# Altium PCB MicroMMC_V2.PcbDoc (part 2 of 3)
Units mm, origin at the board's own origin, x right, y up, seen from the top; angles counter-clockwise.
Board outline 100.01 x 100 mm, 4 copper layers (TOP01, GND02, POWER03, BOTTOM04); 302 components, 195 nets, 1017 pads, 817 vias.
Unrouted connection lines stored in the file: 7.
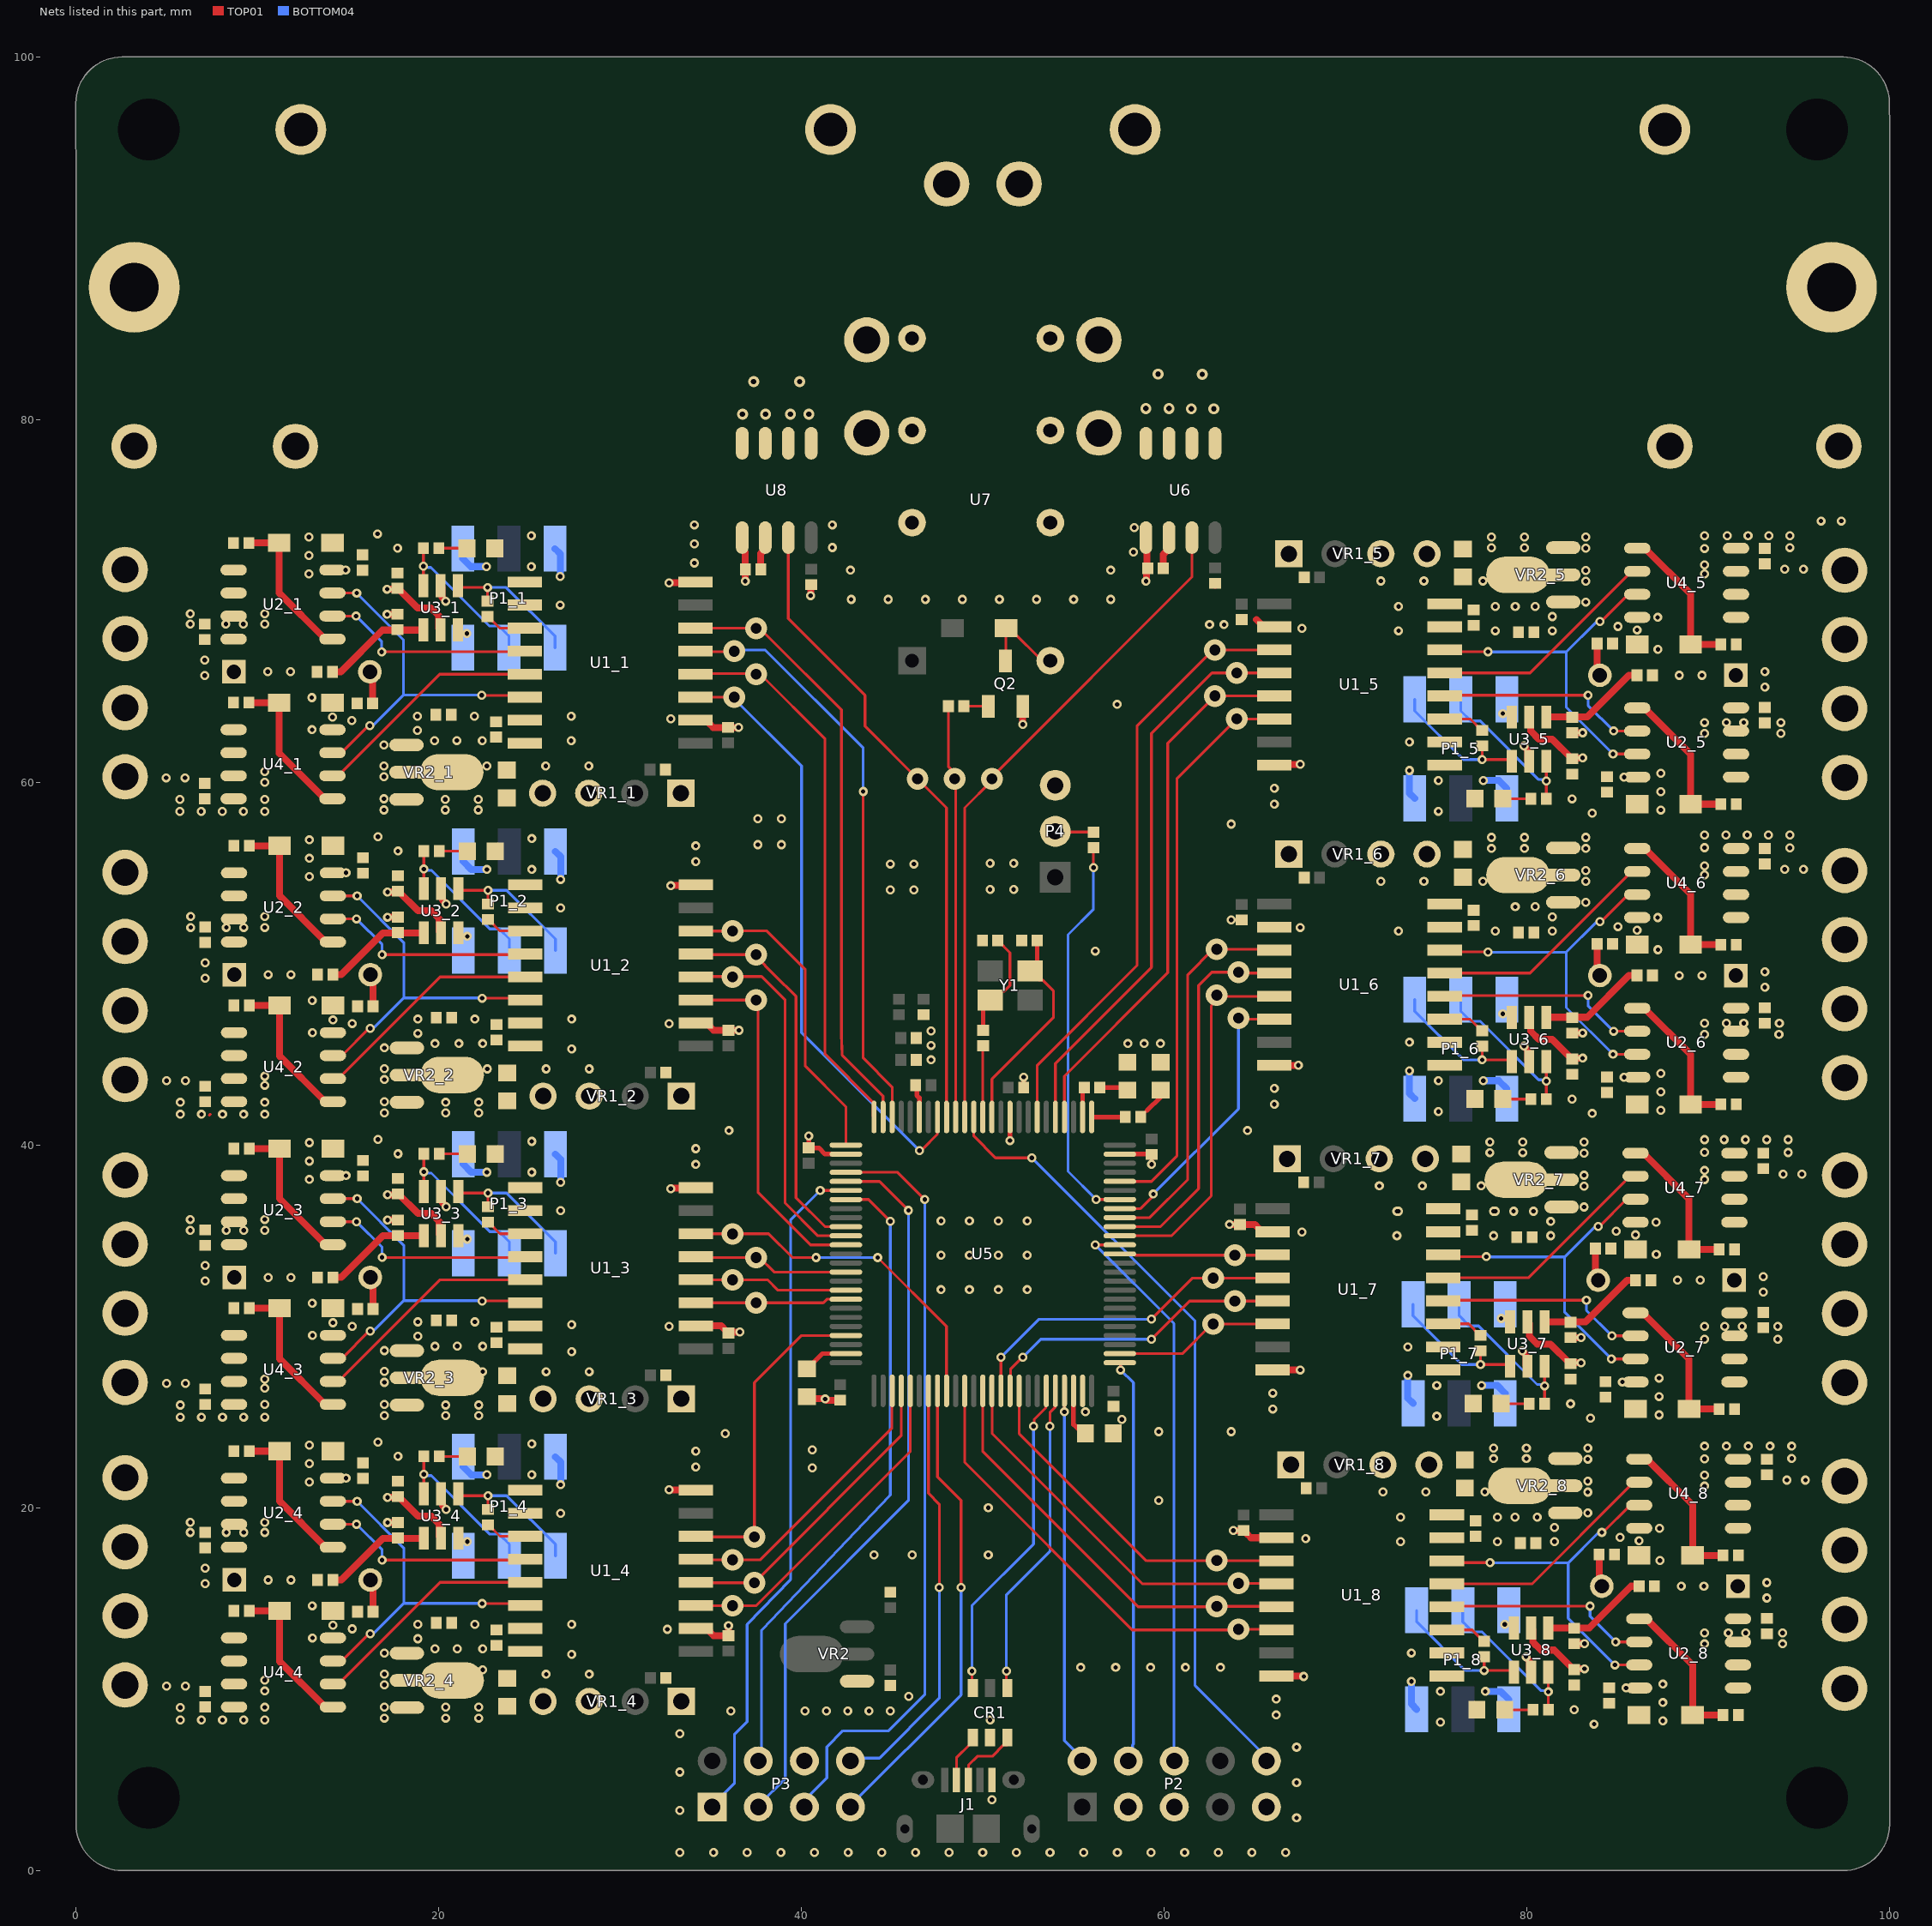
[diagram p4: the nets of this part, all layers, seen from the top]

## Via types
v1: diameter 0.5, hole 0.25, TOP01 to BOTTOM04, tented both sides, 760 vias
v2: diameter 1.2, hole 0.6, TOP01 to BOTTOM04, 35 vias
v3: diameter 0.6, hole 0.3, TOP01 to BOTTOM04, tented both sides, 12 vias
v4: diameter 0.5, hole 0.25, TOP01 to BOTTOM04, 10 vias

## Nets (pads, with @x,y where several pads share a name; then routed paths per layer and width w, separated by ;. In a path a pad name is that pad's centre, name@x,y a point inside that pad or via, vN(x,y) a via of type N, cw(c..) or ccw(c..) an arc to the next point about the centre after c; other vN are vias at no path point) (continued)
+5V_SM: C2_1.2 C2_2.2 C2_3.2 C2_4.2 C2_5.2 C2_6.2 C2_7.2 C2_8.2 C9_1.2 C9_2.2 C9_3.2 C9_4.2 C9_5.2 C9_6.2 C9_7.2 C9_8.2 C10_1.2 C10_2.2 C10_3.2 C10_4.2 C10_5.2 C10_6.2 C10_7.2 C10_8.2 P1_1.2 P1_2.2 P1_3.2 P1_4.2 P1_5.2 P1_6.2 P1_7.2 P1_8.2 U1_1.10 U1_1.16 U1_2.10 U1_2.16 U1_3.10 U1_3.16 U1_4.10 U1_4.16 U1_5.10 U1_5.16 U1_6.10 U1_6.16 U1_7.10 U1_7.16 U1_8.10 U1_8.16 U3_1.5 U3_2.5 U3_3.5 U3_4.5 U3_5.5 U3_6.5 U3_7.5 U3_8.5 VR2_1.1 VR2_2.1 VR2_3.1 VR2_4.1 VR2_5.1 VR2_6.1 VR2_7.1 VR2_8.1 | length 53
  TOP01 w0.152: C10_1.2@17.702,70.654 C10_1.2@17.75,70.702 ; C10_4.2@17.726,20.574 C10_4.2@17.774,20.622 ; C10_3.2@17.726,37.259 C10_3.2@17.774,37.306 ; C10_2.2@17.726,53.954 C10_2.2@17.774,54.002 ; U3_1.5@20.003,68.501 U3_1.5@20.1,68.405 ; U3_4.5@20.027,18.421 U3_4.5@20.123,18.325 ; U3_3.5@20.027,35.106 U3_3.5@20.123,35.01 ; U3_2.5@20.027,51.801 U3_2.5@20.123,51.705 ; U3_7.5@80.032,30.246 U3_7.5@80.129,30.149 ; U3_6.5@80.123,47.046 U3_6.5@80.22,46.949 ; U3_5.5@80.123,63.602 U3_5.5@80.22,63.505 ; U3_8.5@80.233,13.372 U3_8.5@80.33,13.276 ; C10_7.2@82.382,27.949 C10_7.2@82.429,27.997 ; C10_6.2@82.473,44.749 C10_6.2@82.52,44.797 ; C10_5.2@82.473,61.305 C10_5.2@82.52,61.353 ; C10_8.2@82.583,11.075 C10_8.2@82.631,11.123
  TOP01 w0.381: v1(17.15,70.654) C10_1.2@17.702,70.654 ; v1(17.174,20.574) C10_4.2@17.726,20.574 ; v1(17.174,37.259) C10_3.2@17.726,37.259 ; v1(17.174,53.954) C10_2.2@17.726,53.954 ; C10_1.2@17.75,70.702 18.828,69.624 19.558,69.624 20.003,69.179 U3_1.5@20.003,68.501 ; C10_4.2@17.774,20.622 18.851,19.544 19.582,19.544 20.027,19.099 U3_4.5@20.027,18.421 ; C10_3.2@17.774,37.306 18.851,36.229 19.582,36.229 20.027,35.784 U3_3.5@20.027,35.106 ; C10_2.2@17.774,54.002 18.851,52.924 19.582,52.924 20.027,52.479 U3_2.5@20.027,51.801 ; U1_1.16@24.1,62.16 U1_1.16@24.75,62.16 ; U1_4.16@24.123,12.08 U1_4.16@24.773,12.08 ; U1_3.16@24.123,28.765 U1_3.16@24.773,28.765 ; U1_2.16@24.123,45.46 U1_2.16@24.773,45.46 ; U1_7.16@75.382,36.491 U1_7.16@76.032,36.491 ; U1_6.16@75.473,53.291 U1_6.16@76.123,53.291 ; U1_5.16@75.473,69.847 U1_5.16@76.123,69.847 ; U1_8.16@75.583,19.617 U1_8.16@76.233,19.617 ; U3_7.5@80.129,30.149 80.129,29.472 80.573,29.027 81.304,29.027 C10_7.2@82.382,27.949 ; U3_6.5@80.22,46.949 80.22,46.272 80.664,45.827 81.395,45.827 C10_6.2@82.473,44.749 ; U3_5.5@80.22,63.505 80.22,62.828 80.664,62.383 81.395,62.383 C10_5.2@82.473,61.305 ; U3_8.5@80.33,13.276 80.33,12.598 80.775,12.153 81.506,12.153 C10_8.2@82.583,11.075 ; C10_7.2@82.429,27.997 v1(82.982,27.997) ; C10_6.2@82.52,44.797 v1(83.073,44.797) ; C10_5.2@82.52,61.353 v1(83.073,61.353) ; C10_8.2@82.631,11.123 v1(83.183,11.123)
  BOTTOM04 w0.381: P1_1.2@26.407,72.89 26.7,72.598 v1(26.7,71.35) ; P1_4.2@26.431,22.81 26.724,22.518 v1(26.724,21.27) ; P1_3.2@26.431,39.495 26.724,39.202 v1(26.724,37.955) ; P1_2.2@26.431,56.19 26.724,55.898 v1(26.724,54.65) ; v1(73.432,27.301) 73.432,26.053 P1_7.2@73.725,25.76 ; v1(73.523,44.101) 73.523,42.853 P1_6.2@73.815,42.561 ; v1(73.523,60.657) 73.523,59.409 P1_5.2@73.815,59.117 ; v1(73.633,10.427) 73.633,9.179 P1_8.2@73.926,8.887
  other v1: 17.001,11.982 73.633,11.997 19.789,12.22 21.016,12.229 22.424,12.22 18.84,12.782 18.84,13.567 81.517,18.13 81.517,18.915 78.371,19.477 79.341,19.477 80.568,19.477 26.724,19.7 83.356,19.715 17.001,28.667 73.432,28.871 19.789,28.905 21.016,28.914 22.424,28.905 18.84,29.467 18.84,30.252 81.316,35.004 81.316,35.789 78.17,36.351 78.26,36.351 79.268,36.351 80.366,36.351 26.724,36.385 83.155,36.589 17.001,45.362 19.789,45.6 21.106,45.6 22.424,45.6 73.523,45.671 18.84,46.162 18.84,46.947 81.407,51.804 81.407,52.589 26.724,53.08 79.359,53.142 80.457,53.151 83.246,53.389 16.977,62.062 73.523,62.227 19.765,62.3 20.992,62.309 22.4,62.3 18.816,62.862 18.816,63.647 81.407,68.36 81.407,69.145 78.26,69.698 79.359,69.698 80.457,69.698 26.7,69.78 83.246,69.945
+12_SM: C3_1.2 C3_2.2 C3_3.2 C3_4.2 C3_5.2 C3_6.2 C3_7.2 C3_8.2 C4_1.2 C4_2.2 C4_3.2 C4_4.2 C4_5.2 C4_6.2 C4_7.2 C4_8.2 C6_1.2 C6_2.2 C6_3.2 C6_4.2 C6_5.2 C6_6.2 C6_7.2 C6_8.2 D1_1.1 D1_2.1 D1_3.1 D1_4.1 D1_5.1 D1_6.1 D1_7.1 D1_8.1 D2_1.1 D2_2.1 D2_3.1 D2_4.1 D2_5.1 D2_6.1 D2_7.1 D2_8.1 U2_1.4 U2_2.4 U2_3.4 U2_4.4 U2_5.4 U2_6.4 U2_7.4 U2_8.4 U4_1.4 U4_2.4 U4_3.4 U4_4.4 U4_5.4 U4_6.4 U4_7.4 U4_8.4 VR1_1.4 VR1_2.4 VR1_3.4 VR1_4.4 VR1_5.4 VR1_6.4 VR1_7.4 VR1_8.4 VR2_1.3 VR2_2.3 VR2_3.3 VR2_4.3 VR2_5.3 VR2_6.3 VR2_7.3 VR2_8.3 | length 0.1
  TOP01 w0.381: D1_1.1@14.137,73.197 D1_1.1@14.145,73.205 ; D1_4.1@14.161,23.117 D1_4.1@14.169,23.125 ; D1_3.1@14.161,39.801 D1_3.1@14.169,39.81 ; D1_2.1@14.161,56.497 D1_2.1@14.169,56.505 ; D1_7.1@85.986,25.446 D1_7.1@85.995,25.454 ; D1_6.1@86.077,42.246 D1_6.1@86.086,42.254 ; D1_5.1@86.077,58.802 D1_5.1@86.086,58.81 ; D1_8.1@86.188,8.572 D1_8.1@86.196,8.58
  other v1: 87.495,8.247 17.001,8.402 20.382,8.402 22.197,8.402 17.001,9.015 20.382,9.015 22.197,9.015 87.495,9.262 85.471,10.065 87.495,10.277 13.036,12.825 15.224,13.325 14.169,13.52 13.019,14.597 87.338,17.1 86.188,18.177 85.133,18.372 87.321,18.872 12.861,21.42 14.886,21.632 12.861,22.435 83.356,22.682 78.16,22.715 79.975,22.715 78.16,23.294 79.975,23.294 83.356,23.294 12.861,23.45 17.001,25.087 20.382,25.087 22.197,25.087 87.294,25.121 20.382,25.667 22.197,25.667 17.001,25.7 87.294,26.136 85.27,26.939 87.294,27.151 13.036,29.51 15.224,30.01 14.169,30.205 13.019,31.282 87.136,33.974 85.986,35.051 84.932,35.246 87.12,35.746 12.861,38.105 14.886,38.317 12.861,39.12 83.155,39.556 77.959,39.589 79.774,39.589 12.861,40.135 77.959,40.168 79.774,40.168 83.155,40.168 17.001,41.782 20.382,41.782 22.197,41.782 87.385,41.921 20.382,42.362 22.197,42.362 17.001,42.395 87.385,42.936 85.361,43.739 87.385,43.951 13.036,46.205 15.224,46.705 14.169,46.9 13.019,47.977 87.227,50.774 86.077,51.851 85.023,52.046 87.211,52.546 12.861,54.8 14.886,55.012 12.861,55.815 78.05,56.356 79.864,56.356 83.246,56.356 12.861,56.83 78.05,56.968 79.864,56.968 83.246,56.968 16.977,58.482 20.358,58.482 22.173,58.482 87.385,58.477 20.358,59.062 22.173,59.062 16.977,59.095 87.385,59.492 85.361,60.295 87.385,60.507 13.012,62.905 15.2,63.405 14.145,63.6 12.995,64.677 87.227,67.33 86.077,68.407 85.023,68.602 87.211,69.102 12.838,71.5 14.862,71.712 12.838,72.515 83.246,72.912 78.05,72.945 79.864,72.945 12.838,73.53 78.05,73.524 79.864,73.524 83.246,73.524
ADC_I1: U5.15 U6.7 | length 37
  TOP01 w0.152: U5.15@49,41.55 49,58.6 v2@50.5,60.1 ; v2(50.5,60.2) 50.5,60.3 61.533,71.333 U6.7@61.533,73.5
ADC_I2: U5.17 U8.7 | length 35.6
  TOP01 w0.152: U8.7@39.27,73.5 39.27,69.03 43.5,64.8 43.5,63.1 v2(46.4,60.2) 48,58.6 U5.17@48,41.55
BOOT0: R5.1 U5.94 | length 21.7
  TOP01 w0.152: v1(56.1,55.3) R5.1@56.1,56.2 ; v1(56.25,37) U5.94@57.55,37
  BOTTOM04 w0.152: v1(56.1,55.3) 56.1,53 54.7,51.6 54.7,38.55 v1(56.25,37)
EN_1: U1_1.14 U2_1.3 U4_1.3 | length 20.1
  TOP01 w0.152: U4_1.3@14.137,61.635 14.632,61.635 16.131,63.134 v1(16.2,63.134) ; U2_1.3@14.137,70.442 v1(15.475,70.442) 15.508,70.442 v1@15.55,70.4 ; v1(22.365,64.8) 24.649,64.8 U1_1.14@24.75,64.7
  BOTTOM04 w0.152: v1(15.475,70.442) 18.05,67.867 18.05,64.814 ; v1(16.2,63.134) 16.267,63.201 16.437,63.201 18.05,64.814 ; v1(22.365,64.8) 22.351,64.814 18.05,64.814
EN_2: U1_2.14 U2_2.3 U4_2.3 | length 20.1
  TOP01 w0.152: U4_2.3@14.161,44.935 14.655,44.935 16.154,46.434 v1(16.224,46.434) ; U2_2.3@14.161,53.742 v1(15.499,53.742) 15.532,53.742 v1@15.574,53.7 ; v1(22.388,48.1) 24.673,48.1 U1_2.14@24.773,48
  BOTTOM04 w0.152: v1(15.499,53.742) 18.074,51.167 18.074,48.114 ; v1(16.224,46.434) 16.29,46.501 16.46,46.501 18.074,48.114 ; v1(22.388,48.1) 22.374,48.114 18.074,48.114
EN_3: U1_3.14 U2_3.3 U4_3.3 | length 20.1
  TOP01 w0.152: U4_3.3@14.161,28.24 14.655,28.24 16.154,29.739 v1(16.224,29.739) ; U2_3.3@14.161,37.047 v1(15.499,37.047) 15.532,37.047 v1@15.574,37.005 ; v1(22.388,31.405) 24.673,31.405 U1_3.14@24.773,31.305
  BOTTOM04 w0.152: v1(15.499,37.047) 18.074,34.472 18.074,31.419 ; v1(16.224,29.739) 16.29,29.805 16.46,29.805 18.074,31.419 ; v1(22.388,31.405) 22.374,31.419 18.074,31.419
EN_4: U1_4.14 U2_4.3 U4_4.3 | length 20.1
  TOP01 w0.152: U4_4.3@14.161,11.555 14.655,11.555 16.154,13.054 v1(16.224,13.054) ; U2_4.3@14.161,20.362 v1(15.499,20.362) 15.532,20.362 v1@15.574,20.32 ; v1(22.388,14.72) 24.673,14.72 U1_4.14@24.773,14.62
  BOTTOM04 w0.152: v1(15.499,20.362) 18.074,17.787 18.074,14.734 ; v1(16.224,13.054) 16.29,13.121 16.46,13.121 18.074,14.734 ; v1(22.388,14.72) 22.374,14.734 18.074,14.734
EN_5: U1_5.14 U2_5.3 U4_5.3 | length 20.1
  TOP01 w0.152: U1_5.14@75.473,67.307 75.573,67.207 v1(77.858,67.207) ; v1(84.023,68.873) 84.092,68.873 85.591,70.372 U4_5.3@86.086,70.372 ; v1@84.673,61.607 84.715,61.565 v1(84.748,61.565) U2_5.3@86.086,61.565
  BOTTOM04 w0.152: v1(77.858,67.207) 77.872,67.193 82.173,67.193 ; v1(84.023,68.873) 83.956,68.806 83.786,68.806 82.173,67.193 ; v1(84.748,61.565) 82.173,64.14 82.173,67.193
EN_6: U1_6.14 U2_6.3 U4_6.3 | length 20.1
  TOP01 w0.152: U1_6.14@75.473,50.751 75.573,50.651 v1(77.858,50.651) ; v1(84.023,52.317) 84.092,52.317 85.591,53.816 U4_6.3@86.086,53.816 ; v1@84.673,45.051 84.715,45.009 v1(84.748,45.009) U2_6.3@86.086,45.009
  BOTTOM04 w0.152: v1(77.858,50.651) 77.872,50.637 82.173,50.637 ; v1(84.023,52.317) 83.956,52.25 83.786,52.25 82.173,50.637 ; v1(84.748,45.009) 82.173,47.584 82.173,50.637
EN_7: U1_7.14 U2_7.3 U4_7.3 | length 20.1
  TOP01 w0.152: U1_7.14@75.382,33.951 75.482,33.851 v1(77.767,33.851) ; v1(83.932,35.517) 84.001,35.517 85.5,37.016 U4_7.3@85.995,37.016 ; v1@84.582,28.251 84.624,28.209 v1(84.657,28.209) U2_7.3@85.995,28.209
  BOTTOM04 w0.152: v1(77.767,33.851) 77.781,33.837 82.082,33.837 ; v1(83.932,35.517) 83.865,35.45 83.695,35.45 82.082,33.837 ; v1(84.657,28.209) 82.082,30.784 82.082,33.837
EN_8: U1_8.14 U2_8.3 U4_8.3 | length 20.1
  TOP01 w0.152: U1_8.14@75.583,17.077 75.684,16.977 v1(77.968,16.977) ; v1(84.133,18.643) 84.202,18.643 85.702,20.142 U4_8.3@86.196,20.142 ; v1@84.783,11.377 84.825,11.335 v1(84.858,11.335) U2_8.3@86.196,11.335
  BOTTOM04 w0.152: v1(77.968,16.977) 77.982,16.963 82.283,16.963 ; v1(84.133,18.643) 84.067,18.576 83.896,18.576 82.283,16.963 ; v1(84.858,11.335) 82.283,13.91 82.283,16.963
Filter_I1: C25.2 U6.6 | length 1.8
  TOP01 w0.381: C25.2@59.95,71.8 59.95,72.579 60.263,72.893 U6.6@60.263,73.5
Filter_I2: C27.2 U8.6 | length 1.9
  TOP01 w0.381: C27.2@37.753,71.75 37.753,72.616 38,72.864 U8.6@38,73.5
Fv_1: R1_1.1 U1_1.11 | length 2.3
  TOP01 w0.152: R1_1.1@22.69,69.143 22.715,69.143 23.348,68.51 U1_1.11@24.75,68.51
Fv_2: R1_2.1 U1_2.11 | length 2.3
  TOP01 w0.152: R1_2.1@22.713,52.443 22.738,52.443 23.371,51.81 U1_2.11@24.773,51.81
Fv_3: R1_3.1 U1_3.11 | length 2.3
  TOP01 w0.152: R1_3.1@22.713,35.748 22.738,35.748 23.371,35.115 U1_3.11@24.773,35.115
Fv_4: R1_4.1 U1_4.11 | length 2.3
  TOP01 w0.152: R1_4.1@22.713,19.063 22.738,19.063 23.371,18.43 U1_4.11@24.773,18.43
Fv_5: R1_5.1 U1_5.11 | length 2.3
  TOP01 w0.152: U1_5.11@75.473,63.497 76.875,63.497 77.508,62.864 R1_5.1@77.533,62.864
Fv_6: R1_6.1 U1_6.11 | length 2.3
  TOP01 w0.152: U1_6.11@75.473,46.941 76.875,46.941 77.508,46.308 R1_6.1@77.533,46.308
Fv_7: R1_7.1 U1_7.11 | length 2.3
  TOP01 w0.152: U1_7.11@75.382,30.141 76.784,30.141 77.417,29.508 R1_7.1@77.442,29.508
Fv_8: R1_8.1 U1_8.11 | length 2.3
  TOP01 w0.152: U1_8.11@75.583,13.267 76.985,13.267 77.618,12.634 R1_8.1@77.643,12.634
GND: C1_1.1 C1_2.1 C1_3.1 C1_4.1 C1_5.1 C1_6.1 C1_7.1 C1_8.1 C7_1.1 C7_2.1 C7_3.1 C7_4.1 C7_5.1 C7_6.1 C7_7.1 C7_8.1 C10.1 C11.1 C12.1 C13.1 C14.1 C15.1 C16.1 C17.1 C18.1 C19.2 C20.1 C21.1 C22.1 C23.1 C24.1 C25.1 C26.1 C27.1 C28.1 CR1.2 D4.K D5.K J1.5 P2.3 P2.5 P2.9 P3.6 P4.3 Q2.2 U1_1.2 U1_1.8 U1_2.2 U1_2.8 U1_3.2 U1_3.8 U1_4.2 U1_4.8 U1_5.2 U1_5.8 U1_6.2 U1_6.8 U1_7.2 U1_7.8 U1_8.2 U1_8.8 U5.10 U5.20 U5.27 U5.74 U5.99 U6.5 U8.5 VR1_1.1 VR1_2.1 VR1_3.1 VR1_4.1 VR1_5.1 VR1_6.1 VR1_7.1 VR1_8.1 VR2.1 | length 45.4
  TOP01 w0.152: v1@36.9,71.2 v1@36.903,71.203 ; v1(58.35,74.05) v1@58.388,74.012 ; U6.5@58.74,74.012 U6.5@58.993,73.759
  TOP01 w0.254: U1_1.8@34.125,71.075 U1_1.8@34.15,71.05 ; v1(40.4,40.5) 40.4,39.863 40.38,39.843 40.957,39.843 41.295,39.505 42.445,39.505 U5.27@42.45,39.5 ; C13.1@42.102,25.968 C13.1@42.134,25.936 ; C18.1@46.29,43.3 46.357,43.233 46.357,42.743 46.5,42.6 U5.20@46.5,41.55 ; v1(51.5,40.25) U5.10@51.5,41.55 ; C16.1@52.251,43.175 v1@52.251,43.5 ; U5.99@57.55,39.5 59.305,39.5 59.308,39.497 59.308,38.942 v1(59.305,38.939) ; U6.5@58.993,73.5 U6.5@58.993,73.759 ; v1@67.673,10.727 v1(67.7,10.7)
  TOP01 w0.381: v1(32.7,21) 32.715,20.985 34.158,20.985 U1_4.8@34.173,20.97 ; v1(32.7,71) 32.723,71.023 34.123,71.023 U1_1.8@34.15,71.05 ; v1(32.8,37.6) 32.823,37.623 34.141,37.623 U1_3.8@34.173,37.655 ; v1(32.8,54.3) 32.823,54.323 34.146,54.323 U1_2.8@34.173,54.35 ; U1_1.2@34.15,63.43 34.8,63.43 34.909,63.32 34.909,63.253 35.132,63.03 C7_1.1@35.95,63.03 v1(36.525,63.03) ; U1_4.2@34.173,13.35 34.823,13.35 34.933,13.24 34.933,13.173 35.156,12.95 C7_4.1@35.973,12.95 v1(35.973,13.5) ; U1_3.2@34.173,30.035 35.573,30.035 35.839,29.769 35.839,29.744 35.948,29.635 36.065,29.635 36.108,29.677 36.577,29.677 v1(36.6,29.7) ; U1_2.2@34.173,46.73 34.823,46.73 34.933,46.62 34.933,46.553 35.156,46.33 C7_2.1@35.973,46.33 v1(36.548,46.33) ; U8.5@36.73,73.5 36.791,73.439 36.791,72.803 36.903,72.691 36.903,71.885 v1@36.903,71.203 ; C23.1@40.3,26.13 40.407,26.023 41.277,26.023 v1(41.3,26) 41.332,26 41.396,25.936 C13.1@42.134,25.936 ; v1(40.5,70.3) 40.52,70.32 40.52,70.88 C28.1@40.54,70.9 ; v1(52.2,63.2) Q2.2@52.2,64.2 ; U6.5@58.993,73.5 59.047,73.447 59.047,71.853 C25.1@59.1,71.8 59.023,71.723 59.023,71.123 v1(59,71.1) ; C26.1@62.802,70.866 62.803,70.867 C26.1@62.803,70.975 ; v1(63.607,35.621) C7_7.1@64.182,35.621 64.999,35.621 65.223,35.398 65.223,35.33 65.332,35.221 U1_7.2@65.982,35.221 ; v1(63.808,18.747) C7_8.1@64.383,18.747 64.408,18.747 64.518,18.637 64.518,18.613 64.783,18.347 U1_8.2@66.183,18.347 ; 65.09,68.977 U1_5.2@65.314,68.754 ; U1_5.2@65.314,68.686 U1_5.2@65.423,68.577 ; U1_7.8@65.982,27.601 v1(67.5,27.6) ; U1_6.8@66.074,44.4 v1(67.4,44.4) ; U1_5.8@66.073,60.957 66.095,60.978 67.478,60.978 v1(67.5,61) ; U1_8.8@66.183,10.727 v1@67.673,10.727
  other v1: 33.295,1 35.151,1 37.006,1 38.862,1 40.717,1 42.573,1 44.429,1 46.284,1 48.14,1 49.995,1 51.851,1 53.706,1 55.562,1 57.417,1 59.273,1 61.128,1 62.984,1 64.84,1 66.695,1 67.3,2.9 33.295,3.314 50.5,3.9 67.3,4.85 33.295,5.427 67.3,6.8 33.295,7.54 50.4,8.3 66.183,8.577 36.1,8.8 40.2,8.8 41.375,8.8 42.55,8.8 43.725,8.8 44.9,8.8 66.183,9.45 45.92,9.603 55.4,11.2 57.325,11.2 59.25,11.2 61.175,11.2 63.1,11.2 32.6,13.3 44,17.4 46.1,17.4 50.3,17.4 67.8,18.3 50.3,20 59.7,20.4 40.6,22.2 34.173,22.247 34.173,23.12 40.6,23.2 35.8,24.1 59.7,24.2 63.7,24.2 57.665,24.877 55.66,25.291 65.982,25.451 65.982,26.324 32.7,30 47.697,32.03 49.259,32.03 50.859,32.03 52.45,32.03 47.697,33.923 49.259,33.923 50.859,33.923 52.45,33.923 67.6,35.2 47.697,35.823 49.259,35.823 50.859,35.823 52.45,35.823 34.173,38.932 34.173,39.805 36,40.8 64.6,40.8 66.073,42.251 66.073,43.124 52.251,43.75 47.14,44.7 47.14,45.5 58,45.6 58.9,45.6 59.8,45.6 47.14,46.3 32.7,46.7 56.2,50.7 67.5,52 63.698,52.421 44.9,55.5 34.173,55.627 34.173,56.5 63.7,57.7 37.6,58 66.073,58.807 66.073,59.68 32.8,63.5 57.4,64.3 67.6,68.5 62.5,68.7 63.3,68.7 42.739,70.092 44.784,70.092 46.828,70.092 48.873,70.092 50.917,70.092 52.962,70.092 55.006,70.092 57.051,70.092 36.9,71.1 42.7,71.7 57.051,71.7 34.1,72.1 58.3,72.703 41.7,72.95 34.1,73.15 34.1,74.2 41.7,74.2 96.221,74.413 97.34,74.413
  other v4: 44.9,54.067 46.2,54.067 50.4,54.1 51.7,54.1 46.2,55.5 50.4,55.533 51.7,55.533 37.6,56.567 38.9,56.567 38.9,58
GND_SM: C2_1.1 C2_2.1 C2_3.1 C2_4.1 C2_5.1 C2_6.1 C2_7.1 C2_8.1 C3_1.1 C3_2.1 C3_3.1 C3_4.1 C3_5.1 C3_6.1 C3_7.1 C3_8.1 C4_1.1 C4_2.1 C4_3.1 C4_4.1 C4_5.1 C4_6.1 C4_7.1 C4_8.1 C6_1.1 C6_2.1 C6_3.1 C6_4.1 C6_5.1 C6_6.1 C6_7.1 C6_8.1 C9_1.1 C9_2.1 C9_3.1 C9_4.1 C9_5.1 C9_6.1 C9_7.1 C9_8.1 C10_1.1 C10_2.1 C10_3.1 C10_4.1 C10_5.1 C10_6.1 C10_7.1 C10_8.1 C11_1.1 C11_2.1 C11_3.1 C11_4.1 C11_5.1 C11_6.1 C11_7.1 C11_8.1 C12_1.1 C12_2.1 C12_3.1 C12_4.1 C12_5.1 C12_6.1 C12_7.1 C12_8.1 Csm_1.2 Csm_2.2 Csm_3.2 Csm_4.2 Csm_5.2 Csm_6.2 Csm_7.2 Csm_8.2 D3_1.K D3_2.K D3_3.K D3_4.K D3_5.K D3_6.K D3_7.K D3_8.K GND_SM.1 P1_1.6 P1_2.6 P1_3.6 P1_4.6 P1_5.6 P1_6.6 P1_7.6 P1_8.6 R4_1.1 R4_2.1 R4_3.1 R4_4.1 R4_5.1 R4_6.1 R4_7.1 R4_8.1 U1_1.9 U1_1.15 U1_2.9 U1_2.15 U1_3.9 U1_3.15 U1_4.9 U1_4.15 U1_5.9 U1_5.15 U1_6.9 U1_6.15 U1_7.9 U1_7.15 U1_8.9 U1_8.15 U2_1.7 U2_2.7 U2_3.7 U2_4.7 U2_5.7 U2_6.7 U2_7.7 U2_8.7 U3_1.2 U3_2.2 U3_3.2 U3_4.2 U3_5.2 U3_6.2 U3_7.2 U3_8.2 U4_1.7 U4_2.7 U4_3.7 U4_4.7 U4_5.7 U4_6.7 U4_7.7 U4_8.7 VR1_1.3 VR1_2.3 VR1_3.3 VR1_4.3 VR1_5.3 VR1_6.3 VR1_7.3 VR1_8.3 VR2_1.2 VR2_2.2 VR2_3.2 VR2_4.2 VR2_5.2 VR2_6.2 VR2_7.2 VR2_8.2 | length 43.3
  TOP01 w0.381: Csm_1.2@16.2,66.1 16.35,65.95 C6_1.1@16.35,64.313 ; Csm_4.2@16.224,16.02 16.374,15.87 C6_4.1@16.374,14.233 ; Csm_3.2@16.224,32.705 16.374,32.555 C6_3.1@16.374,30.918 ; Csm_2.2@16.224,49.4 16.374,49.25 C6_2.1@16.374,47.613 ; v1(17.15,69.268) R4_1.1@17.725,69.268 ; v1(17.174,19.188) R4_4.1@17.749,19.188 ; v1(17.174,35.873) R4_3.1@17.749,35.873 ; v1(17.174,52.568) R4_2.1@17.749,52.568 ; U3_1.2@20.1,70.843 20.189,70.754 20.189,70.215 20.379,70.025 v1(20.379,69.993) ; U3_4.2@20.123,20.763 20.212,20.674 20.212,20.135 20.403,19.945 v1(20.403,19.913) ; U3_3.2@20.123,37.448 20.212,37.359 20.212,36.82 20.403,36.63 v1(20.403,36.598) ; U3_2.2@20.123,54.143 20.212,54.054 20.212,53.515 20.403,53.325 v1(20.403,53.293) ; v1(79.753,28.658) 79.753,28.626 79.943,28.435 79.943,27.896 U3_7.2@80.032,27.808 ; v1(79.844,45.458) 79.844,45.426 80.034,45.235 80.034,44.696 U3_6.2@80.123,44.608 ; v1(79.844,62.014) 79.844,61.982 80.034,61.791 80.034,61.252 U3_5.2@80.123,61.164 ; v1(79.954,11.784) 79.954,11.752 80.145,11.561 80.145,11.022 U3_8.2@80.233,10.934 ; R4_7.1@82.407,29.383 v1(82.982,29.383) ; R4_6.1@82.498,46.183 v1(83.073,46.183) ; R4_5.1@82.498,62.739 v1(83.073,62.739) ; R4_8.1@82.608,12.509 v1(83.183,12.509) ; C6_7.1@83.782,34.338 83.782,32.701 Csm_7.2@83.932,32.551 ; C6_6.1@83.873,51.138 83.873,49.501 Csm_6.2@84.023,49.351 ; C6_5.1@83.873,67.694 83.873,66.057 Csm_5.2@84.023,65.907 ; C6_8.1@83.983,17.464 83.983,15.827 Csm_8.2@84.133,15.677
  BOTTOM04 w0.381: P1_1.6@21.327,72.89 21.327,72.345 21.772,71.9 v1(22.625,71.9) ; P1_4.6@21.351,22.81 21.351,22.265 21.795,21.82 v1(22.648,21.82) ; P1_3.6@21.351,39.495 21.351,38.949 21.795,38.505 v1(22.648,38.505) ; P1_2.6@21.351,56.19 21.351,55.645 21.795,55.2 v1(22.648,55.2) ; v1(77.507,26.751) 78.36,26.751 78.805,26.306 P1_7.6@78.805,25.76 ; v1(77.598,43.551) 78.451,43.551 78.895,43.106 P1_6.6@78.895,42.561 ; v1(77.598,60.107) 78.451,60.107 78.895,59.662 P1_5.6@78.895,59.117 ; v1(77.708,9.877) 78.561,9.877 79.006,9.432 P1_8.6@79.006,8.887
  other v1: 83.706,8.072 75.233,8.177 82.608,8.862 75.233,9.877 10.4,9.9 4.997,10.17 6.024,10.17 17.001,10.234 10.4,10.5 17.001,10.832 25.924,10.82 28.293,10.82 22.424,11.065 27.324,11.92 89.8,12.5 94.1,12.5 89.8,13.1 91.108,13.1 92.071,13.1 94.1,13.1 21.986,13.567 27.324,13.567 73.033,18.13 78.371,18.13 6.3,18.645 8.286,18.645 9.249,18.645 10.4,18.645 6.3,19.2 10.4,19.2 73.033,19.477 83.356,20.865 72.063,20.877 74.433,20.877 77.685,20.877 89.8,21.2 83.356,21.463 94.333,21.527 95.36,21.527 89.8,21.8 25.124,21.82 17.749,22.835 25.124,23.52 16.651,23.625 83.505,24.946 75.032,25.051 82.407,25.736 10.4,26.6 75.032,26.751 4.997,26.855 6.024,26.855 17.001,26.919 10.4,27.1 17.001,27.517 22.424,27.505 25.924,27.505 28.293,27.505 27.324,28.605 89.8,29.3 93.832,29.3 89.8,30 90.907,30 91.87,30 93.832,30 27.324,30.105 21.986,30.252 72.832,35.004 78.17,35.004 6.3,35.3 8.286,35.3 9.249,35.3 10.4,35.3 6.3,35.9 10.4,35.9 72.832,36.351 72.923,36.351 71.862,37.751 74.232,37.751 77.483,37.751 83.155,37.739 89.8,38.1 83.155,38.336 94.132,38.401 95.159,38.401 25.124,38.505 89.8,38.6 17.749,39.52 25.124,40.205 16.651,40.31 83.596,41.746 75.123,41.851 82.498,42.536 10.4,43.3 4.997,43.55 6.024,43.55 75.123,43.551 17.001,43.614 10.4,43.8 22.672,44.2 25.924,44.2 28.293,44.2 17.001,44.212 27.324,45.3 89.8,46.1 93.9,46.1 89.8,46.726 90.998,46.726 91.961,46.726 93.923,46.726 21.986,46.947 27.324,46.947 72.923,51.804 78.26,51.804 6.324,52 8.286,52 9.249,52 10.4,52 6.324,52.6 10.4,52.6 83.246,54.539 71.953,54.551 74.323,54.551 77.574,54.551 89.8,54.9 83.246,55.136 25.124,55.2 94.223,55.201 95.25,55.201 89.8,55.4 17.749,56.215 25.124,56.9 16.651,57.005 83.596,58.302 75.123,58.407 82.498,59.092 10.4,60 75.123,60.107 4.973,60.25 6,60.25 16.977,60.314 10.4,60.6 16.977,60.912 22.648,60.9 25.9,60.9 28.27,60.9 27.3,62.3 89.8,62.7 94,62.7 89.8,63.3 90.998,63.3 91.961,63.3 94,63.3 21.962,63.647 27.3,63.647 72.923,68.36 78.26,68.36 6.3,68.725 8.262,68.725 9.225,68.725 10.4,68.725 6.3,69.3 10.4,69.3 72.923,69.698 71.953,71.107 74.323,71.107 77.574,71.107 83.246,71.095 89.8,71.5 83.246,71.693 94.223,71.757 95.25,71.757 25.1,71.9 89.8,72 17.725,72.915 25.1,73.6 16.627,73.705
GPIO1: P3.8 U5.57 | length 23.4
  TOP01 w0.152: U5.57@47,26.45 47,20.8 47.6,20.2 v1(47.6,15.6)
  BOTTOM04 w0.152: P3.8@42.78,6.2 44.3,6.2 47.6,9.5 v1(47.6,15.6)
GPIO2: P3.7 U5.58 | length 25.8
  TOP01 w0.152: U5.58@47.5,26.45 47.5,21.7 48.8,20.4 v1(48.8,15.6)
  BOTTOM04 w0.152: P3.7@42.78,3.66 48.8,9.68 v1(48.8,15.6)
GPIO_EN1: U1_1.3 U5.18 | length 33.6
  TOP01 w0.152: U1_1.3@34.15,64.7 v2@36.2,64.7 ; v1(46.5,39.7) 46.567,39.767 46.667,39.767 47.487,40.587 47.487,41.537 U5.18@47.5,41.55
  BOTTOM04 w0.152: v2@36.2,64.7 40,60.9 40,46.2 v1(46.5,39.7)
  other v2: 36.3,64.7
GPIO_EN2: U1_2.3 U5.37 | length 20.1
  TOP01 w0.152: U1_2.3@34.173,48 37.6,48 37.6,37.4 40.5,34.5 U5.37@42.45,34.5
  other v2: 37.5,48
GPIO_EN3: U1_3.3 U5.43 | length 8.4
  TOP01 w0.152: U1_3.3@34.173,31.305 41.205,31.305 41.4,31.5 U5.43@42.45,31.5
  other v2: 37.5,31.3
GPIO_EN4: U1_4.3 U5.55 | length 18.7
  TOP01 w0.152: U1_4.3@34.173,14.62 34.193,14.6 37.5,14.6 46,23.1 U5.55@46,26.45
  other v2: 36.2,14.6
GPIO_EN5: U1_5.3 U5.7 | length 33.1
  TOP01 w0.152: U5.7@53,41.55 53,44.4 58.5,49.9 58.5,63.1 62.707,67.307 U1_5.3@66.073,67.307
  other v2: 62.8,67.3
GPIO_EN6: U1_6.3 U5.92 | length 21.3
  TOP01 w0.152: U5.92@57.55,36 59.2,36 61.3,38.1 61.3,49.4 62.7,50.8 v2(62.9,50.8) 66.024,50.8 U1_6.3@66.073,50.751
GPIO_EN7: U1_7.3 U5.88 | length 8.5
  TOP01 w0.152: U5.88@57.55,34 58.345,34 58.411,33.933 v2(63.9,33.933) 65.964,33.933 U1_7.3@65.982,33.951
GPIO_EN8: U1_8.3 U5.67 | length 19.5
  TOP01 w0.152: U5.67@52,26.45 52,24.1 59.023,17.077 62.877,17.077 v2(62.9,17.1) 62.923,17.077 U1_8.3@66.183,17.077
GPIO_Relay: R11.1 U5.16 | length 22.8
  TOP01 w0.152: R11.1@48.1,64.2 48.1,60.883 48.5,60.483 48.5,60.2 U5.16@48.5,41.55
  other v2: 48.45,60.2
IN1_1: U1_1.12 U2_1.2 | length 11.8
  TOP01 w0.152: U2_1.2@14.137,69.172 v1(15.44,69.172) ; v1(16.85,67.2) 24.71,67.2 U1_1.12@24.75,67.24
  BOTTOM04 w0.152: v1(15.44,69.172) 16.85,67.762 v1(16.85,67.2)
IN1_2: U1_2.12 U2_2.2 | length 11.8
  TOP01 w0.152: U2_2.2@14.161,52.472 v1(15.464,52.472) ; v1(16.874,50.5) 24.733,50.5 U1_2.12@24.773,50.54
  BOTTOM04 w0.152: v1(15.464,52.472) 16.874,51.062 v1(16.874,50.5)
IN1_3: U1_3.12 U2_3.2 | length 11.8
  TOP01 w0.152: U2_3.2@14.161,35.777 v1(15.464,35.777) ; v1(16.874,33.805) 24.733,33.805 U1_3.12@24.773,33.845
  BOTTOM04 w0.152: v1(15.464,35.777) 16.874,34.367 v1(16.874,33.805)
IN1_4: U1_4.12 U2_4.2 | length 11.8
  TOP01 w0.152: U2_4.2@14.161,19.092 v1(15.464,19.092) ; v1(16.874,17.12) 24.733,17.12 U1_4.12@24.773,17.16
  BOTTOM04 w0.152: v1(15.464,19.092) 16.874,17.682 v1(16.874,17.12)
IN1_5: U1_5.12 U2_5.2 | length 11.8
  TOP01 w0.152: U1_5.12@75.473,64.767 75.513,64.807 v1(83.373,64.807) ; v1(84.782,62.835) U2_5.2@86.086,62.835
  BOTTOM04 w0.152: v1(83.373,64.807) 83.373,64.245 v1(84.782,62.835)
IN1_6: U1_6.12 U2_6.2 | length 11.8
  TOP01 w0.152: U1_6.12@75.473,48.211 75.513,48.251 v1(83.373,48.251) ; v1(84.782,46.279) U2_6.2@86.086,46.279
  BOTTOM04 w0.152: v1(83.373,48.251) 83.373,47.689 v1(84.782,46.279)
IN1_7: U1_7.12 U2_7.2 | length 11.8
  TOP01 w0.152: U1_7.12@75.382,31.411 75.422,31.451 v1(83.282,31.451) ; v1(84.691,29.479) U2_7.2@85.995,29.479
  BOTTOM04 w0.152: v1(83.282,31.451) 83.282,30.889 v1(84.691,29.479)
IN1_8: U1_8.12 U2_8.2 | length 11.8
  TOP01 w0.152: U1_8.12@75.583,14.537 75.623,14.577 v1(83.483,14.577) ; v1(84.893,12.605) U2_8.2@86.196,12.605
  BOTTOM04 w0.152: v1(83.483,14.577) 83.483,14.015 v1(84.893,12.605)
IN2_1: U1_1.13 U4_1.2 | length 12.2
  TOP01 w0.152: 14.723,60.647 20.046,65.97 U1_1.13@24.75,65.97
IN2_2: U1_2.13 U4_2.2 | length 12.2
  TOP01 w0.152: 14.747,43.947 20.069,49.27 U1_2.13@24.773,49.27
IN2_3: U1_3.13 U4_3.2 | length 12.2
  TOP01 w0.152: 14.747,27.252 20.069,32.575 U1_3.13@24.773,32.575
IN2_4: U1_4.13 U4_4.2 | length 12.2
  TOP01 w0.152: 14.747,10.567 20.069,15.89 U1_4.13@24.773,15.89
IN2_5: U1_5.13 U4_5.2 | length 12.2
  TOP01 w0.152: U1_5.13@75.473,66.037 80.177,66.037 85.5,71.36
IN2_6: U1_6.13 U4_6.2 | length 12.2
  TOP01 w0.152: U1_6.13@75.473,49.481 80.177,49.481 85.5,54.804
IN2_7: U1_7.13 U4_7.2 | length 12.2
  TOP01 w0.152: U1_7.13@75.382,32.681 80.086,32.681 85.409,38.004
IN2_8: U1_8.13 U4_8.2 | length 12.2
  TOP01 w0.152: U1_8.13@75.583,15.807 80.287,15.807 85.61,21.13
IP+I1: L2.2 U6.1 U6.2
  other v3: 61.503,80.6 62.741,80.6 62.1,82.5
IP+I2: P15.1 U7.8 U8.1 U8.2
  other v3: 39.39,80.306 40.4,80.306 39.9,82.1
IP-I1: P9.1 U6.3 U6.4 U7.9
  other v3: 58.991,80.616 60.261,80.616 59.663,82.516
IP-I2: L3.1 U8.3 U8.4
  other v3: 36.75,80.306 38.02,80.306 37.365,82.1
LED1: R6.2 U5.1 | length 1.9
  TOP01 w0.254: U5.1@56,41.55 R6.2@57.85,41.55
LED2: R7.2 U5.2 | length 1.7
  TOP01 w0.152: R7.2@55.5,43.076 R7.2@55.599,43.175
  TOP01 w0.254: U5.2@55.5,41.55 R7.2@55.5,43.076
NetC5_1_1: C5_1.1 D1_1.2 U2_1.1 | length 8.4
  TOP01 w0.381: C5_1.1@9.537,73.205 D1_1.2@11.195,73.205 11.195,70.446 13.74,67.902 U2_1.1@14.137,67.902
NetC5_2_1: C5_2.1 D1_2.2 U2_2.1 | length 8.4
  TOP01 w0.152: U2_2.1@13.764,51.202 U2_2.1@14.161,51.202
  TOP01 w0.381: C5_2.1@9.561,56.505 D1_2.2@11.219,56.505 11.219,53.746 U2_2.1@13.764,51.202
NetC5_3_1: C5_3.1 D1_3.2 U2_3.1 | length 8.4
  TOP01 w0.152: U2_3.1@13.764,34.507 U2_3.1@14.161,34.507
  TOP01 w0.381: C5_3.1@9.561,39.81 D1_3.2@11.219,39.81 11.219,37.051 U2_3.1@13.764,34.507
NetC5_4_1: C5_4.1 D1_4.2 U2_4.1 | length 8.4
  TOP01 w0.152: U2_4.1@13.764,17.822 U2_4.1@14.161,17.822
  TOP01 w0.381: C5_4.1@9.561,23.125 D1_4.2@11.219,23.125 11.219,20.366 U2_4.1@13.764,17.822
NetC5_5_1: C5_5.1 D1_5.2 U2_5.1 | length 8.4
  TOP01 w0.152: U2_5.1@86.086,64.105 U2_5.1@86.483,64.105
  TOP01 w0.381: U2_5.1@86.483,64.105 89.027,61.56 D1_5.2@89.027,58.802 C5_5.1@90.686,58.802
NetC5_6_1: C5_6.1 D1_6.2 U2_6.1 | length 8.4
  TOP01 w0.152: U2_6.1@86.086,47.549 U2_6.1@86.483,47.549
  TOP01 w0.381: U2_6.1@86.483,47.549 89.027,45.004 D1_6.2@89.027,42.246 C5_6.1@90.686,42.246
NetC5_7_1: C5_7.1 D1_7.2 U2_7.1 | length 8.4
  TOP01 w0.152: U2_7.1@85.995,30.749 U2_7.1@86.392,30.749
  TOP01 w0.381: U2_7.1@86.392,30.749 88.936,28.204 D1_7.2@88.936,25.446 C5_7.1@90.595,25.446
NetC5_8_1: C5_8.1 D1_8.2 U2_8.1 | length 8.4
  TOP01 w0.152: U2_8.1@86.196,13.875 U2_8.1@86.593,13.875
  TOP01 w0.381: U2_8.1@86.593,13.875 89.138,11.33 D1_8.2@89.138,8.572 C5_8.1@90.796,8.572
NetC8_1_1: C8_1.1 D2_1.2 U4_1.1 | length 8.4
  TOP01 w0.381: C8_1.1@9.525,64.4 D2_1.2@11.195,64.4 11.195,61.612 13.712,59.095 U4_1.1@14.137,59.095
NetC8_2_1: C8_2.1 D2_2.2 U4_2.1 | length 8.4
  TOP01 w0.152: U4_2.1@13.736,42.395 U4_2.1@14.161,42.395
  TOP01 w0.381: C8_2.1@9.549,47.7 D2_2.2@11.219,47.7 11.219,44.912 U4_2.1@13.736,42.395
NetC8_3_1: C8_3.1 D2_3.2 U4_3.1 | length 8.4
  TOP01 w0.152: U4_3.1@13.736,25.7 U4_3.1@14.161,25.7
  TOP01 w0.381: C8_3.1@9.549,31.005 D2_3.2@11.219,31.005 11.219,28.217 U4_3.1@13.736,25.7
NetC8_4_1: C8_4.1 D2_4.2 U4_4.1 | length 8.4
  TOP01 w0.152: U4_4.1@13.736,9.015 U4_4.1@14.161,9.015
  TOP01 w0.381: C8_4.1@9.549,14.32 D2_4.2@11.219,14.32 11.219,11.532 U4_4.1@13.736,9.015
NetC8_5_1: C8_5.1 D2_5.2 U4_5.1 | length 8.4
  TOP01 w0.152: U4_5.1@86.086,72.912 U4_5.1@86.511,72.912
  TOP01 w0.381: U4_5.1@86.511,72.912 89.027,70.395 D2_5.2@89.027,67.607 C8_5.1@90.698,67.607
NetC8_6_1: C8_6.1 D2_6.2 U4_6.1 | length 8.4
  TOP01 w0.152: U4_6.1@86.086,56.356 U4_6.1@86.511,56.356
  TOP01 w0.381: U4_6.1@86.511,56.356 89.027,53.839 D2_6.2@89.027,51.051 C8_6.1@90.698,51.051
NetC8_7_1: C8_7.1 D2_7.2 U4_7.1 | length 8.4
  TOP01 w0.152: U4_7.1@85.995,39.556 U4_7.1@86.42,39.556
  TOP01 w0.381: U4_7.1@86.42,39.556 88.936,37.039 D2_7.2@88.936,34.251 C8_7.1@90.607,34.251
NetC8_8_1: C8_8.1 D2_8.2 U4_8.1 | length 8.4
  TOP01 w0.152: U4_8.1@86.196,22.682 U4_8.1@86.621,22.682
  TOP01 w0.381: U4_8.1@86.621,22.682 89.138,20.165 D2_8.2@89.138,17.377 C8_8.1@90.808,17.377
NetC21_2: C21.2 R8.2 Y1.3 | length 6.6
  TOP01 w0.152: Y1.3@50.4,48 50.897,48.497 51.197,48.497 51.5,48.8 51.5,50.608 C21.2@50.825,51.283
  TOP01 w0.254: R8.2@50.018,46.325 50.018,47.618 Y1.3@50.4,48 Y1.3@50.825,48.425
NetC22_2: C22.2 U5.12 Y1.1 | length 12
  TOP01 w0.152: U5.12@50.5,41.55 50.5,43.639 53.892,47.031 53.892,48.508 53.299,49.101 53.099,49.101 Y1.1@52.6,49.6
  TOP01 w0.254: Y1.1@52.6,49.6 52.999,49.999 C22.2@52.999,51.283
NetC23_2: C23.2 U5.49 | length 2.5
  TOP01 w0.254: C23.2@40.3,27.67 40.325,27.67 41.155,28.5 U5.49@42.45,28.5
NetC24_2: C24.2 U5.73 | length 2.5
  TOP01 w0.254: U5.73@55,26.45 55,24.595 55.47,24.125 C24.2@55.47,24.1
NetD3_1_A: D3_1.A R3_1.1 | length 1.6
  TOP01 w0.152: R3_1.1@20,72.915 21.54,72.915 D3_1.A@21.55,72.905
NetD3_2_A: D3_2.A R3_2.1 | length 1.6
  TOP01 w0.152: R3_2.1@20.023,56.215 21.563,56.215 D3_2.A@21.573,56.205
NetD3_3_A: D3_3.A R3_3.1 | length 1.6
  TOP01 w0.152: R3_3.1@20.023,39.52 21.563,39.52 D3_3.A@21.573,39.51
NetD3_4_A: D3_4.A R3_4.1 | length 1.6
  TOP01 w0.152: R3_4.1@20.023,22.835 21.563,22.835 D3_4.A@21.573,22.825
NetD3_5_A: D3_5.A R3_5.1 | length 1.6
  TOP01 w0.152: D3_5.A@78.673,59.102 78.683,59.092 R3_5.1@80.223,59.092
NetD3_6_A: D3_6.A R3_6.1 | length 1.6
  TOP01 w0.152: D3_6.A@78.673,42.546 78.683,42.536 R3_6.1@80.223,42.536
NetD3_7_A: D3_7.A R3_7.1 | length 1.6
  TOP01 w0.152: D3_7.A@78.582,25.746 78.592,25.736 R3_7.1@80.132,25.736
NetD3_8_A: D3_8.A R3_8.1 | length 1.6
  TOP01 w0.152: D3_8.A@78.783,8.872 78.793,8.862 R3_8.1@80.333,8.862
NetD4_A: D4.A R6.1 | length 2
  TOP01 w0.152: R6.1@58.7,41.55 58.7,41.575 58.924,41.799 58.949,41.799 59.057,41.907 ; D4.A@59.801,42.651 D4.A@59.801,43.035
  TOP01 w0.254: 59.057,41.907 D4.A@59.801,42.651
NetD5_A: D5.A R7.1 | length 1.6
  TOP01 w0.152: D5.A@57.835,43.175 D5.A@57.975,43.035
  TOP01 w0.254: R7.1@56.449,43.175 D5.A@57.835,43.175
NetP4_2: P4.2 R5.2 | length 2.1
  TOP01 w0.152: P4.2@54,57.26 56.09,57.26 R5.2@56.1,57.25
NetQ2_1: Q2.1 R11.2 | length 1.4
  TOP01 w0.152: R11.2@48.95,64.2 Q2.1@50.3,64.2
NetR8_1: R8.1 U5.13 | length 3.9
  TOP01 w0.152: U5.13@50,41.55 50,45.457 R8.1@50.018,45.475
NRST: P2.10 U5.14 | length 43.2
  TOP01 w0.152: U5.14@49.5,41.55 49.5,40.5 50.7,39.3 v1(52.7,39.3)
  BOTTOM04 w0.152: v1(52.7,39.3) 61.7,30.3 61.7,11.419 61.701,11.418 61.701,10.982 61.7,10.981 61.7,10.2 65.62,6.28 P2.10@65.62,6.2
Out1: P12.1 U7.13
OUT1_1: C5_1.2 OUT1_1.1 U2_1.5 U2_1.6
OUT1_2: C5_2.2 OUT1_2.1 U2_2.5 U2_2.6
OUT1_3: C5_3.2 OUT1_3.1 U2_3.5 U2_3.6
OUT1_4: C5_4.2 OUT1_4.1 U2_4.5 U2_4.6
OUT1_5: C5_5.2 OUT1_5.1 U2_5.5 U2_5.6
OUT1_6: C5_6.2 OUT1_6.1 U2_6.5 U2_6.6
OUT1_7: C5_7.2 OUT1_7.1 U2_7.5 U2_7.6
OUT1_8: C5_8.2 OUT1_8.1 U2_8.5 U2_8.6
Out2: P13.1 U7.4
OUT2_1: C8_1.2 OUT2_1.1 U4_1.5 U4_1.6
OUT2_2: C8_2.2 OUT2_2.1 U4_2.5 U4_2.6
OUT2_3: C8_3.2 OUT2_3.1 U4_3.5 U4_3.6
OUT2_4: C8_4.2 OUT2_4.1 U4_4.5 U4_4.6
OUT2_5: C8_5.2 OUT2_5.1 U4_5.5 U4_5.6
OUT2_6: C8_6.2 OUT2_6.1 U4_6.5 U4_6.6
OUT2_7: C8_7.2 OUT2_7.1 U4_7.5 U4_7.6
OUT2_8: C8_8.2 OUT2_8.1 U4_8.5 U4_8.6
PB0_1: P1_1.1 R1_1.2 U3_1.1 | length 8.3
  TOP01 w0.152: U3_1.1@21.05,70.488 U3_1.1@21.05,70.843 21.143,70.75 v1(22.69,70.75) R1_1.2@22.69,69.993
  BOTTOM04 w0.152: v1(22.69,70.75) 23.723,70.75 26.407,68.065 P1_1.1@26.407,67.43
PB0_2: P1_2.1 R1_2.2 U3_2.1 | length 8.3
  TOP01 w0.152: U3_2.1@21.073,53.788 U3_2.1@21.073,54.143 21.167,54.05 v1(22.713,54.05) R1_2.2@22.713,53.293
  BOTTOM04 w0.152: v1(22.713,54.05) 23.746,54.05 26.431,51.365 P1_2.1@26.431,50.73
PB0_3: P1_3.1 R1_3.2 U3_3.1 | length 8.3
  TOP01 w0.152: U3_3.1@21.073,37.093 U3_3.1@21.073,37.448 21.167,37.355 v1(22.713,37.355) R1_3.2@22.713,36.598
  BOTTOM04 w0.152: v1(22.713,37.355) 23.746,37.355 26.431,34.67 P1_3.1@26.431,34.035
PB0_4: P1_4.1 R1_4.2 U3_4.1 | length 8.3
  TOP01 w0.152: U3_4.1@21.073,20.408 U3_4.1@21.073,20.763 21.167,20.67 v1(22.713,20.67) R1_4.2@22.713,19.913
  BOTTOM04 w0.152: v1(22.713,20.67) 23.746,20.67 26.431,17.985 P1_4.1@26.431,17.35
PB0_5: P1_5.1 R1_5.2 U3_5.1 | length 8.3
  TOP01 w0.152: R1_5.2@77.533,62.014 v1(77.533,61.257) 79.08,61.257 U3_5.1@79.173,61.164 U3_5.1@79.173,61.519
  BOTTOM04 w0.152: P1_5.1@73.815,64.577 73.815,63.942 76.5,61.257 v1(77.533,61.257)
PB0_6: P1_6.1 R1_6.2 U3_6.1 | length 8.3
  TOP01 w0.152: R1_6.2@77.533,45.458 v1(77.533,44.701) 79.08,44.701 U3_6.1@79.173,44.608 U3_6.1@79.173,44.963
  BOTTOM04 w0.152: P1_6.1@73.815,48.021 73.815,47.386 76.5,44.701 v1(77.533,44.701)
PB0_7: P1_7.1 R1_7.2 U3_7.1 | length 8.3
  TOP01 w0.152: R1_7.2@77.442,28.658 v1(77.442,27.901) 78.989,27.901 U3_7.1@79.082,27.808 U3_7.1@79.082,28.163
  BOTTOM04 w0.152: P1_7.1@73.725,31.221 73.725,30.586 76.409,27.901 v1(77.442,27.901)
PB0_8: P1_8.1 R1_8.2 U3_8.1 | length 8.3
  TOP01 w0.152: R1_8.2@77.643,11.784 v1(77.643,11.027) 79.19,11.027 U3_8.1@79.283,10.934 U3_8.1@79.283,11.289
  BOTTOM04 w0.152: P1_8.1@73.926,14.347 73.926,13.712 76.61,11.027 v1(77.643,11.027)
PB1_1: P1_1.3 R3_1.2 U3_1.3 | length 9
  TOP01 w0.152: U3_1.3@19.15,70.843 R3_1.2@19.15,72.915
  BOTTOM04 w0.152: v1(19.15,71.924) 19.216,71.857 19.407,71.857 19.413,71.852 19.567,71.852 22.794,68.624 23.308,68.624 23.867,68.065 P1_1.3@23.867,67.43
PB1_2: P1_2.3 R3_2.2 U3_2.3 | length 9
  TOP01 w0.152: U3_2.3@19.173,54.143 R3_2.2@19.173,56.215
  BOTTOM04 w0.152: v1(19.173,55.224) 19.24,55.157 19.43,55.157 19.436,55.152 19.59,55.152 22.818,51.924 23.332,51.924 23.891,51.365 P1_2.3@23.891,50.73
PB1_3: P1_3.3 R3_3.2 U3_3.3 | length 9
  TOP01 w0.152: U3_3.3@19.173,37.448 R3_3.2@19.173,39.52
  BOTTOM04 w0.152: v1(19.173,38.529) 19.24,38.462 19.43,38.462 19.436,38.456 19.59,38.456 22.818,35.229 23.332,35.229 23.891,34.67 P1_3.3@23.891,34.035
PB1_4: P1_4.3 R3_4.2 U3_4.3 | length 9
  TOP01 w0.152: U3_4.3@19.173,20.763 R3_4.2@19.173,22.835
  BOTTOM04 w0.152: v1(19.173,21.844) 19.24,21.777 19.43,21.777 19.436,21.772 19.59,21.772 22.818,18.544 23.332,18.544 23.891,17.985 P1_4.3@23.891,17.35
PB1_5: P1_5.3 R3_5.2 U3_5.3 | length 9
  TOP01 w0.152: R3_5.2@81.073,59.092 U3_5.3@81.073,61.164
  BOTTOM04 w0.152: P1_5.3@76.355,64.577 76.355,63.942 76.914,63.383 77.429,63.383 80.656,60.155 80.81,60.155 80.816,60.149 81.007,60.149 v1(81.073,60.083)
PB1_6: P1_6.3 R3_6.2 U3_6.3 | length 9
  TOP01 w0.152: R3_6.2@81.073,42.536 U3_6.3@81.073,44.608
  BOTTOM04 w0.152: P1_6.3@76.355,48.021 76.355,47.386 76.914,46.827 77.429,46.827 80.656,43.599 80.81,43.599 80.816,43.593 81.007,43.593 v1(81.073,43.527)
PB1_7: P1_7.3 R3_7.2 U3_7.3 | length 9
  TOP01 w0.152: R3_7.2@80.982,25.736 U3_7.3@80.982,27.808
  BOTTOM04 w0.152: P1_7.3@76.265,31.221 76.265,30.586 76.823,30.027 77.338,30.027 80.565,26.799 80.719,26.799 80.725,26.793 80.916,26.793 v1(80.982,26.727)
PB1_8: P1_8.3 R3_8.2 U3_8.3 | length 9
  TOP01 w0.152: R3_8.2@81.183,8.862 U3_8.3@81.183,10.934
  BOTTOM04 w0.152: P1_8.3@76.466,14.347 76.466,13.712 77.025,13.153 77.539,13.153 80.767,9.925 80.92,9.925 80.926,9.919 81.117,9.919 v1(81.183,9.853)
PB2_1: R2_1.1 R4_1.2 U3_1.4 | length 5.8
  TOP01 w0.152: U3_1.4@19.145,68.4 U3_1.4@19.15,68.405
  TOP01 w0.381: R2_1.1@14.262,66.1 14.595,66.1 16.895,68.4 U3_1.4@19.145,68.4
PB2_2: R2_2.1 R4_2.2 U3_2.4 | length 5.8
  TOP01 w0.152: U3_2.4@19.168,51.7 U3_2.4@19.173,51.705
  TOP01 w0.381: R2_2.1@14.286,49.4 14.618,49.4 16.918,51.7 U3_2.4@19.168,51.7
PB2_3: R2_3.1 R4_3.2 U3_3.4 | length 5.8
  TOP01 w0.152: U3_3.4@19.168,35.005 U3_3.4@19.173,35.01
  TOP01 w0.381: R2_3.1@14.286,32.705 14.618,32.705 16.918,35.005 U3_3.4@19.168,35.005
PB2_4: R2_4.1 R4_4.2 U3_4.4 | length 5.8
  TOP01 w0.152: U3_4.4@19.168,18.32 U3_4.4@19.173,18.325
  TOP01 w0.381: R2_4.1@14.286,16.02 14.618,16.02 16.918,18.32 U3_4.4@19.168,18.32
PB2_5: R2_5.1 R4_5.2 U3_5.4 | length 5.8
  TOP01 w0.152: U3_5.4@81.073,63.602 U3_5.4@81.078,63.607
  TOP01 w0.381: U3_5.4@81.078,63.607 83.328,63.607 85.628,65.907 R2_5.1@85.961,65.907
PB2_6: R2_6.1 R4_6.2 U3_6.4 | length 5.8
  TOP01 w0.152: U3_6.4@81.073,47.046 U3_6.4@81.078,47.051
  TOP01 w0.381: U3_6.4@81.078,47.051 83.328,47.051 85.628,49.351 R2_6.1@85.961,49.351
PB2_7: R2_7.1 R4_7.2 U3_7.4 | length 5.8
  TOP01 w0.152: U3_7.4@80.982,30.246 U3_7.4@80.987,30.251
  TOP01 w0.381: U3_7.4@80.987,30.251 83.237,30.251 85.537,32.551 R2_7.1@85.87,32.551
PB2_8: R2_8.1 R4_8.2 U3_8.4 | length 5.8
  TOP01 w0.152: U3_8.4@81.183,13.372 U3_8.4@81.188,13.377
  TOP01 w0.381: U3_8.4@81.188,13.377 83.438,13.377 85.738,15.677 R2_8.1@86.071,15.677
PB3_1: P1_1.5 U3_1.6 | length 0.6
  TOP01 w0.152: U3_1.6@21.05,68.405 21.245,68.21 v1(21.55,68.21)
PB3_2: P1_2.5 U3_2.6 | length 0.6
  TOP01 w0.152: U3_2.6@21.073,51.705 21.268,51.51 v1(21.573,51.51)
PB3_3: P1_3.5 U3_3.6 | length 0.6
  TOP01 w0.152: U3_3.6@21.073,35.01 21.268,34.815 v1(21.573,34.815)
PB3_4: P1_4.5 U3_4.6 | length 0.6
  TOP01 w0.152: U3_4.6@21.073,18.325 21.268,18.13 v1(21.573,18.13)
PB3_5: P1_5.5 U3_5.6 | length 0.6
  TOP01 w0.152: v1(78.673,63.797) 78.978,63.797 U3_5.6@79.173,63.602
PB3_6: P1_6.5 U3_6.6 | length 0.6
  TOP01 w0.152: v1(78.673,47.241) 78.978,47.241 U3_6.6@79.173,47.046
PB3_7: P1_7.5 U3_7.6 | length 0.6
  TOP01 w0.152: v1(78.582,30.441) 78.887,30.441 U3_7.6@79.082,30.246
PB3_8: P1_8.5 U3_8.6 | length 0.6
  TOP01 w0.152: v1(78.783,13.567) 79.088,13.567 U3_8.6@79.283,13.372
PWM_IN11: U1_1.5 U5.23 | length 32.6
  TOP01 w0.152: U1_1.5@34.15,67.24 34.19,67.2 v2@36.3,67.2 ; v1(43.4,59.5) 43.4,44.8 45,43.2 U5.23@45,41.55
  BOTTOM04 w0.152: v2@36.3,67.2 36.402,67.302 37.998,67.302 43.4,61.9 v1(43.4,59.5)
  other v2: 36.3,67.233
PWM_IN12: U1_2.5 U5.35 | length 21.1
  TOP01 w0.152: U1_2.5@34.173,50.54 34.213,50.5 v2(37.5,50.5) 37.5,50.4 38.5,49.4 39.7,48.2 39.7,37.1 41.3,35.5 U5.35@42.45,35.5
PWM_IN13: U1_3.5 U5.40 | length 8.6
  TOP01 w0.152: U1_3.5@34.173,33.845 34.218,33.8 37.692,33.8 38.492,33 U5.40@42.45,33
  other v2: 37.5,33.8
PWM_IN14: U1_4.5 U5.53 | length 15.9
  TOP01 w0.152: U1_4.5@34.173,17.16 34.2,17.133 v2(36.2,17.133) 37.733,17.133 44.976,24.376 44.976,26.426 U5.53@45,26.45
PWM_IN15: U1_5.5 U5.4 | length 29.9
  TOP01 w0.152: U5.4@54.5,41.55 54.5,43.8 60.2,49.5 60.2,62.167 v2(62.8,64.767) U1_5.5@66.073,64.767
PWM_IN16: U1_6.5 U5.90 | length 20.4
  TOP01 w0.152: U5.90@57.55,35 60.398,35 62.597,37.199 62.597,47.68 62.9,47.983 v2(62.9,48.267) 62.967,48.2 66.062,48.2 U1_6.5@66.073,48.211
PWM_IN17: U1_7.5 U5.66 | length 17.2
  TOP01 w0.152: U5.66@51.5,26.45 51.524,26.474 51.524,27.645 52.179,28.3 v1(52.2,28.3) ; v1(59.3,29.3) 61.4,31.4 65.971,31.4 U1_7.5@65.982,31.411
  BOTTOM04 w0.152: v1(52.2,28.3) 53.2,29.3 v1(59.3,29.3)
  other v2: 63.9,31.4
PWM_IN18: U1_8.5 U5.63 | length 23.1
  TOP01 w0.152: U5.63@50,26.45 50,23.1 58.563,14.537 62.87,14.537 v2(62.9,14.567) 66.154,14.567 U1_8.5@66.183,14.537
PWM_IN21: U1_1.4 U5.25 | length 30.6
  TOP01 w0.152: U1_1.4@34.15,65.97 34.18,66 37.7,66 41.3,62.4 41.3,45.01 43.958,42.352 43.958,41.592 U5.25@44,41.55
  other v2: 37.5,65.967
PWM_IN22: U1_2.4 U5.36 | length 20.8
  TOP01 w0.152: U1_2.4@34.173,49.27 34.204,49.3 36.2,49.3 37.8,49.3 39.1,48 39.1,36.8 40.9,35 U5.36@42.45,35
  other v2: 36.2,49.267
PWM_IN23: U1_3.4 U5.42 | length 8.5
  TOP01 w0.152: U1_3.4@34.173,32.575 38.125,32.575 38.7,32 U5.42@42.45,32
  other v2: 36.2,32.567
PWM_IN24: U1_4.4 U5.54 | length 17.2
  TOP01 w0.152: U1_4.4@34.173,15.89 34.197,15.867 v2(37.4,15.867) 45.5,23.967 U5.54@45.5,26.45
PWM_IN25: U1_5.4 U5.5 | length 31.5
  TOP01 w0.152: U5.5@54,41.55 54,44.5 59.3,49.8 59.3,62.7 62.637,66.037 U1_5.4@66.073,66.037
  other v2: 64,66.033
PWM_IN26: U1_6.4 U5.91 | length 20.9
  TOP01 w0.152: U5.91@57.55,35.5 59.8,35.5 61.9,37.6 61.9,48.8 62.633,49.533 v2(64.1,49.533) ; v2@64.1,49.481 U1_6.4@66.073,49.481
PWM_IN27: U1_7.4 U5.65 | length 18.6
  TOP01 w0.152: U5.65@51,26.45 v1(51,28.3) ; v1(59.3,30.4) 61.567,32.667 65.968,32.667 U1_7.4@65.982,32.681
  BOTTOM04 w0.152: v1(51,28.3) 53.1,30.4 v1(59.3,30.4)
  other v2: 62.7,32.667
PWM_IN28: U1_8.4 U5.64 | length 21.5
  TOP01 w0.152: U5.64@50.5,26.45 50.513,26.437 50.513,24.087 58.793,15.807 64.074,15.807 v2(64.1,15.833) 66.157,15.833 U1_8.4@66.183,15.807
Rcharge1: P10.1 U7.11
Rcharge2: P14.1 U7.6
Relay: D6.1 Q2.3 U7.16 | length 4.5
  TOP01 w0.152: Q2.3@51.275,66.725 51.275,68.7 51.275,68.625 51.824,68.076 51.899,68.076 53.006,66.969
SPI_MISO: P3.1 U5.31 | length 37.7
  TOP01 w0.152: v1(41.034,37.5) U5.31@42.45,37.5
  BOTTOM04 w0.152: P3.1@35.16,3.66 36.3,4.8 36.3,7.5 37,8.2 37,13.563 39.4,16.037 39.4,35.866 v1(41.034,37.5)
SPI_MOSI: P3.4 U5.32 | length 35.4
  TOP01 w0.152: U5.32@42.45,37 43.7,37 44.317,36.383 v1(44.9,35.8)
  BOTTOM04 w0.152: P3.4@37.7,6.2 37.8,6.3 37.8,13.19 37.8,13.252 37.842,13.296 44.857,20.655 ccw(c44.748,20.761) 44.859,20.656 44.9,20.7 v1(44.9,35.8)
SPI_NSS: P3.5 U5.29 | length 42.5
  TOP01 w0.152: U5.29@42.45,38.5 45.3,38.5 v1(46.8,37)
  BOTTOM04 w0.152: P3.5@40.24,3.66 40.24,3.94 41.4,5.1 41.4,6.816 42.284,7.7 44.8,7.7 46.8,9.7 v1(46.8,37)
SPI_SCK: P3.3 U5.30 | length 40.2
  TOP01 w0.152: U5.30@42.45,38 44.3,38 45.558,36.742 v1(45.9,36.4)
  BOTTOM04 w0.152: P3.3@37.7,3.66 39.107,5.067 39.107,13.607 45.9,20.4 v1(45.9,36.4)
StackBottom1: L2.1 P7.1
StackBottom2: P18.1 P19.1
StackTop1: P5.1 P6.1
StackTop2: L3.2 P17.1
SWCLK: P2.4 U5.76 | length 22.2
  TOP01 w0.152: U5.76@57.55,28 57.6,27.95 v1(57.6,27.6)
  BOTTOM04 w0.152: v1(57.6,27.6) 58.3,26.9 58.3,6.963 58.258,6.921 58.258,6.458 P2.4@58,6.2
SWDIO: P2.2 U5.72 | length 20.6
  TOP01 w0.152: v1(54.5,25.291) U5.72@54.5,26.45
  BOTTOM04 w0.152: v1(54.5,25.291) 54.5,7.16 P2.2@55.46,6.2
SWO: P2.6 U5.89 | length 31.4
  TOP01 w0.152: v1(56.2,34.5) U5.89@57.55,34.5
  BOTTOM04 w0.152: v1(56.2,34.5) 60.54,30.16 P2.6@60.54,6.2
TIM_Fv1: U1_1.6 U5.24 | length 33.3
  TOP01 w0.152: U1_1.6@34.15,68.51 34.16,68.5 37.692,68.5 38.182,68.01 38.19,68.01 42.2,64 42.2,46.13 42.245,44.955 44.5,42.7 U5.24@44.5,41.55
  other v2: 37.5,68.5
TIM_Fv2: U1_2.6 U5.26 | length 17.5
  TOP01 w0.152: U1_2.6@34.173,51.81 34.183,51.8 v2(36.2,51.8) 36.21,51.81 38.09,51.81 40.2,49.7 40.2,44.371 42.45,42.121 U5.26@42.45,40
TIM_Fv3: U1_3.6 U5.59 | length 19.5
  TOP01 w0.152: U1_3.6@34.173,35.115 38.185,35.115 39.5,33.8 v1(40.8,33.8) ; v1(44.2,33.8) 48,30 U5.59@48,26.45
  BOTTOM04 w0.152: v1(40.8,33.8) v1(44.2,33.8)
  other v2: 36.2,35.1
TIM_Fv4: U1_4.6 U5.47 | length 17.9
  TOP01 w0.152: U1_4.6@34.173,18.43 34.203,18.4 37.2,18.4 v2@37.3,18.5 ; v2(37.4,18.4) v2@37.3,18.5 ; U5.47@42.45,29.5 40,29.5 37.4,26.9 37.4,18.6 v2@37.3,18.5
TIM_Fv5: U1_5.6 U5.96 | length 31.3
  TOP01 w0.152: U5.96@57.55,38 59.3,38 60.7,39.4 60.7,60.2 v2(64,63.5) ; v2@64,63.497 U1_5.6@66.073,63.497
TIM_Fv6: U1_6.6 U5.93 | length 15.8
  TOP01 w0.152: U5.93@57.55,36.5 58.7,36.5 v1@59.4,37.2 ; v2(64.1,47) 64.159,46.941 U1_6.6@66.073,46.941
  BOTTOM04 w0.152: v1(59.4,37.3) 64.1,42 v2(64.1,47)
TIM_Fv7: U1_7.6 U5.77 | length 9.1
  TOP01 w0.152: U5.77@57.55,28.5 61,28.5 62.633,30.133 65.974,30.133 U1_7.6@65.982,30.141
  other v2: 62.7,30.133
TIM_Fv8: U1_8.6 U5.61 | length 25
  TOP01 w0.152: U5.61@49,26.45 49,22.5 58.233,13.267 64.067,13.267 v2(64.1,13.3) 66.15,13.3 U1_8.6@66.183,13.267
USB_CONN_D+: CR1.3 J1.3 | length 3.4
  TOP01 w0.152: J1.3@49.2,5 49.214,5.014 49.214,5.814 49.7,6.3 50.525,6.3 51.147,6.922 51.337,6.922 CR1.3@51.35,6.935
USB_CONN_D-: CR1.1 J1.2 | length 2.4
  TOP01 w0.152: J1.2@48.55,5 48.55,6.225 49.26,6.935 CR1.1@49.45,6.935
USB_D+: CR1.4 U5.71 | length 17.9
  TOP01 w0.152: CR1.4@51.3,9.715 v1(51.3,11) ; v1(53.7,24.5) 53.7,25.25 53.976,25.526 53.976,26.426 U5.71@54,26.45
  BOTTOM04 w0.152: v1(51.3,11) 51.3,15.2 53.7,17.6 v1(53.7,24.5)
USB_D-: CR1.6 U5.70 | length 18.3
  TOP01 w0.152: CR1.6@49.4,9.815 v1@49.4,11.1 ; v1@52.8,24.4 52.83,24.43 52.83,24.879 53.476,25.524 53.476,26.426 U5.70@53.5,26.45
  BOTTOM04 w0.152: v1@49.4,11.1 49.4,14.6 52.8,18 v1@52.8,24.4
  other v1: 49.4,11 52.8,24.5
VCap_1: C11_1.2 C12_1.2 Csm_1.1 R2_1.2 U2_1.8 U4_1.8 VCap_1.1
  other v1: 5.727,58.4 6.895,58.4 8.063,58.4 9.232,58.4 10.4,58.4 5.727,59.06 10.4,59.06 7.1,65.9 10.57,66.1 11.82,66.1 7.1,66.75
VCap_2: C11_2.2 C12_2.2 Csm_2.1 R2_2.2 U2_2.8 U4_2.8 VCap_2.1 | length 0.1
  TOP01 w0.152: 7.35,41.65 7.4,41.7
  other v1: 5.751,41.7 6.913,41.7 8.075,41.7 9.238,41.7 10.4,41.7 5.751,42.36 10.4,42.36 7.124,49.2 10.594,49.4 11.844,49.4 7.124,50.05
VCap_3: C11_3.2 C12_3.2 Csm_3.1 R2_3.2 U2_3.8 U4_3.8 VCap_3.1
  other v1: 5.751,25 6.913,25 8.075,25 9.238,25 10.4,25 5.751,25.665 10.4,25.7 7.124,32.505 10.594,32.705 11.844,32.705 7.124,33.355
VCap_4: C11_4.2 C12_4.2 Csm_4.1 R2_4.2 U2_4.8 U4_4.8 VCap_4.1
  other v1: 5.751,8.3 6.913,8.3 8.075,8.3 9.238,8.3 10.4,8.3 5.751,8.98 10.4,9 7.124,15.82 10.594,16.02 11.844,16.02 7.124,16.67
VCap_5: C11_5.2 C12_5.2 Csm_5.1 R2_5.2 U2_5.8 U4_5.8 VCap_5.1
  other v1: 93.123,65.257 88.402,65.907 89.652,65.907 93.123,66.107 89.8,72.9 94.496,72.947 89.8,73.607 91.049,73.607 92.198,73.607 93.347,73.607 94.496,73.607
VCap_6: C11_6.2 C12_6.2 Csm_6.1 R2_6.2 U2_6.8 U4_6.8 VCap_6.1
  other v1: 93.123,48.701 88.402,49.351 89.652,49.351 93.123,49.551 89.8,56.4 94.496,56.391 89.8,57.1 90.974,57.1 92.148,57.1 93.322,57.1 94.496,57.1
VCap_7: C11_7.2 C12_7.2 Csm_7.1 R2_7.2 U2_7.8 U4_7.8 VCap_7.1
  other v1: 93.032,31.901 88.311,32.551 89.561,32.551 93.032,32.751 89.8,39.6 94.405,39.591 89.8,40.3 90.876,40.3 92.052,40.3 93.229,40.3 94.405,40.3
VCap_8: C11_8.2 C12_8.2 Csm_8.1 R2_8.2 U2_8.8 U4_8.8 VCap_8.1
  other v1: 93.233,15.027 88.513,15.677 89.763,15.677 93.233,15.877 89.8,22.7 94.606,22.717 89.8,23.4 91.002,23.4 92.203,23.4 93.405,23.4 94.606,23.4
pads on no net: J1.4 J1.6 J1.7 J1.8 J1.9 J1.10 J1.11 P1_1.4 P1_2.4 P1_3.4 P1_4.4 P1_5.4 P1_6.4 P1_7.4 P1_8.4 P2.7 P2.8 U5.3 U5.8 U5.9 U5.33 U5.34 U5.38 U5.39 U5.41 U5.44 U5.45 U5.46 U5.48 U5.51 U5.52 U5.56 U5.60 U5.62 U5.68 U5.69 U5.78 U5.79 U5.80 U5.81 U5.82 U5.83 U5.84 U5.85 U5.86 U5.87 U5.95 U5.97 U5.98 Y1.2 Y1.4

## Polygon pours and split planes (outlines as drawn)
3.3VA on TOP01 "TOP01-3.3VA" (solid, pour order 948): 46.14,40.79 46.14,43.5 45.775,43.5 45.775,47.526 44.64,47.526 44.64,44.26 45.36,43.54 45.36,43.5 45.36,40.79
GND on TOP01 "NONET_L04_P-001" (solid, pour order 921): 62,71.275 63.6,71.275 63.6,69.3 67.023,69.3 67.023,67.9 62,67.9
+5 on TOP01 "TOP01-+5" (solid, pour order 932): 32.659,27.9 36.7,27.9 36.7,29.085 29.8,29.085 29.8,24.6 32.1,24.6 32.1,27.341
+5 on TOP01 "NONET_L04_P-001" (solid, pour order 933): 36.6,44.5 32.1,44.5 32.1,41.3 29.8,41.3 29.8,45.78 36.6,45.78
+5 on TOP01 "NONET_L04_P-001" (solid, pour order 934): 62,74.4 62,71.4 63.7,71.4 63.7,69.5 70.3,69.5 70.3,74 68.2,74 68.2,70.7 65.123,70.7 65.123,74.377 65.1,74.4
+5 on TOP01 "NONET_L04_P-001" (solid, pour order 935): 63.6,52.971 70.4,52.971 70.4,55 70.4,57.4 68.2,57.4 68.2,54.2 63.6,54.2
+5 on TOP01 "NONET_L04_P-001" (solid, pour order 936): 63.602,36.145 70.402,36.145 70.402,38.302 70.402,40.574 68.202,40.574 68.202,37.571 63.602,37.571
